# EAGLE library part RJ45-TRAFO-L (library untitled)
RJ45 socket with integrated magnetics and LEDs Naming: AmphenolLMJ1998824110DL1T39J TMERJ45-TRAFO-L Author: Petr Kalandra Datasheet: http://zefiryn.tme.pl/dok/zlacza/rjtrafol.PDF
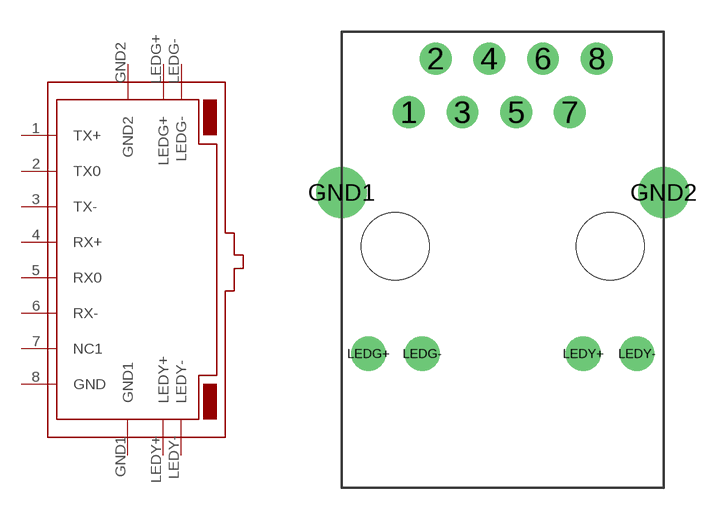
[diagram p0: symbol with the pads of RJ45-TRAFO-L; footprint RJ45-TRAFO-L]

Designator prefix -

## RJ45-TRAFO-L  [RJ45-TRAFO-L]
1  TX+
2  TX0
3  TX-
4  RX+
5  RX0
6  RX-
7  NC1  nc
8  GND  pwr
GND1  GND1  pwr
GND2  GND2  pwr
LEDG+  LEDG+
LEDG-  LEDG-
LEDY+  LEDY+
LEDY-  LEDY-

## Footprint RJ45-TRAFO-L (pad centres in mm)
RJ45 with LED pins
drill 1 round: 1 -4.445,6.35; 2 -3.175,8.89; 3 -1.905,6.35; 4 -0.635,8.89; 5 0.635,6.35; 6 1.905,8.89; 7 3.175,6.35; 8 4.445,8.89
drill 1.6 round: GND1 -7.62,2.54; GND2 7.62,2.54
drill 1.1 round: LEDG+ -6.35,-5.08; LEDG- -3.81,-5.08; LEDY+ 3.81,-5.08; LEDY- 6.35,-5.08
hole 3.2 at -5.08,0
hole 3.2 at 5.08,0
